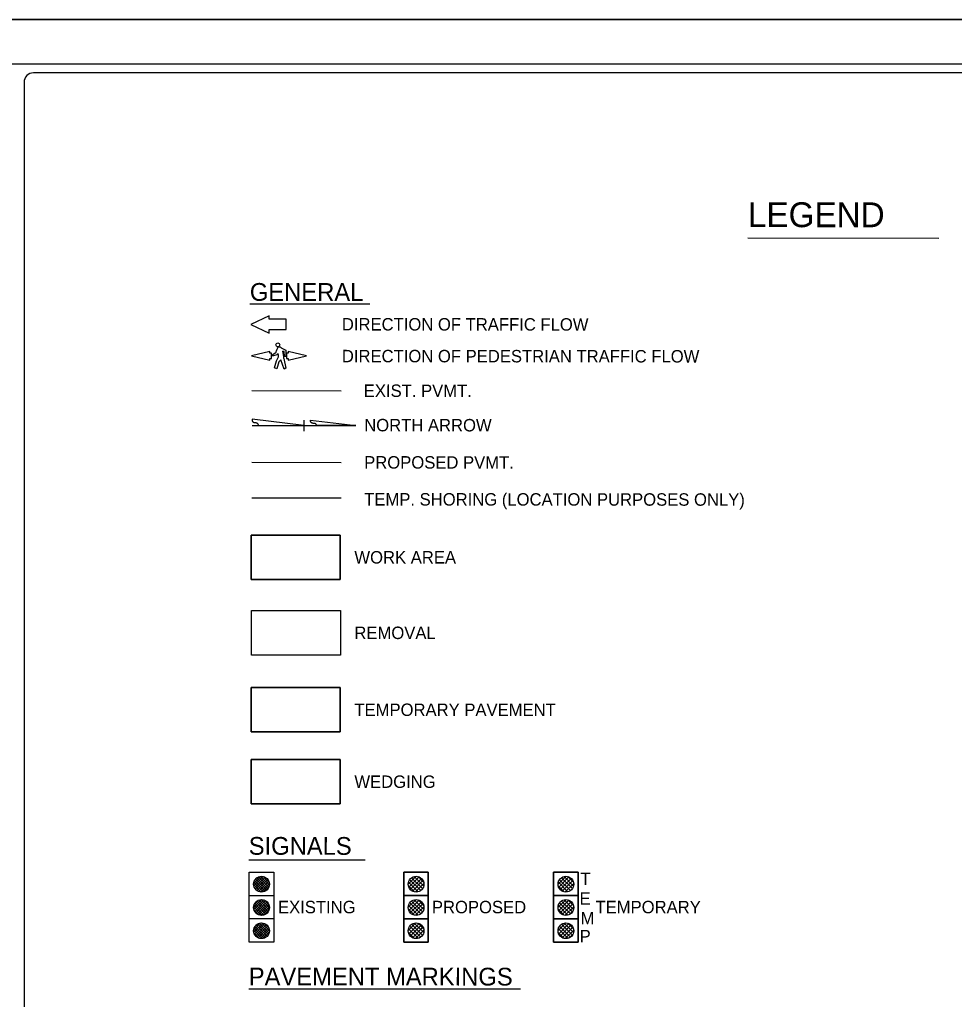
# Model space of a CAD drawing. Extents: x 1403867 to 1405555, y 486423 to 487523.
# Drawn here: x 1404600 to 1405127, y 486971 to 487523 of the extents above; entities that cross this region are included whole.
import ezdxf

# ---------------------------------------------------------------- set-up
doc = ezdxf.new("R2010")
doc.units = 0
for name, color, linetype in [('Black Area Fill Shapes', 7, 'Continuous'), ('DEV BORDER CELL', 7, 'Continuous'), ('DEV SIGNALIZED INTERSECTION CELL', 7, 'Continuous'), ('Gray Area Fill Shapes', 7, 'Continuous'), ('Old_Level_10', 7, 'Continuous'), ('Sheet Plot Border Outside CELL', 7, 'Continuous'), ('Temp Shoring', 7, 'Continuous')]:
    doc.layers.add(name, color=color, linetype=linetype)

msp = doc.modelspace()

# ---------------------------------------------------------------- linework, layer by layer
at = {"layer": 'Black Area Fill Shapes'}
for p, q in [((1404744.88, 487335.56), (1404745.05, 487336.55)), ((1404747.68, 487338.08), (1404750.17, 487336.59)), ((1404750.17, 487336.59), (1404750.2, 487333.12)), ((1404742.39, 487333.93), (1404744.88, 487335.56)), ((1404742.78, 487333.38), (1404742.39, 487333.93)), ((1404745.07, 487334.14), (1404742.78, 487333.38)), ((1404744.95, 487330.73), (1404746.19, 487332.99)), ((1404745.85, 487334.85), (1404745.07, 487334.14)), ((1404747.35, 487331.15), (1404746.38, 487330.17)), ((1404749.33, 487325.96), (1404747.35, 487331.15)), ((1404749.26, 487335.94), (1404748.45, 487336.11)), ((1404749.02, 487332.05), (1404750.3, 487326.64)), ((1404749.49, 487333.12), (1404749.26, 487335.94)), ((1404750.2, 487333.12), (1404749.49, 487333.12)), ((1404743.88, 487326.68), (1404744.95, 487330.73)), ((1404745.21, 487326.25), (1404743.88, 487326.68)), ((1404746.38, 487330.17), (1404745.21, 487326.25)), ((1404750.3, 487326.64), (1404749.33, 487325.96))]:
    msp.add_line(p, q, dxfattribs=at)
for centre, radius, start, end in [((1404748.22, 487336.02), 3.22, 140.1678, 170.5556), ((1404746.39, 487337.54), 0.84, 96.8806, 140.1678), ((1404746.55, 487336.2), 2.19, 59.1458, 96.8806), ((1404740.78, 487332.97), 5.41, 0.2881, 20.3672), ((1404740.78, 487332.97), 8.29, 353.6356, 22.2339)]:
    msp.add_arc(centre, radius, start, end, dxfattribs=at)
at = {"layer": 'DEV BORDER CELL'}
for p, q in [((1405520.08, 487497.72), (1404040.64, 487497.72)), ((1405520.08, 487492.72), (1404608.13, 487492.72)), ((1404602.84, 487487.44), (1404602.84, 486458)), ((1405010.4, 487399.84), (1405117.8, 487399.76)), ((1404729.97, 487362.8), (1404797.57, 487362.76)), ((1404740.89, 487356.07), (1404730.55, 487351.21)), ((1404740.89, 487354.1), (1404740.89, 487356.07)), ((1404750.49, 487354.09), (1404740.89, 487354.1)), ((1404750.48, 487348.3), (1404750.49, 487354.09)), ((1404730.55, 487351.21), (1404740.88, 487346.33)), ((1404740.88, 487346.33), (1404740.88, 487348.31)), ((1404740.88, 487348.31), (1404750.48, 487348.3)), ((1404741.22, 487335.9), (1404730.88, 487333.47)), ((1404730.88, 487333.47), (1404741.21, 487331.03)), ((1404741.21, 487331.03), (1404741.22, 487332.02)), ((1404741.22, 487334.91), (1404741.22, 487335.9)), ((1404742.15, 487334.91), (1404741.22, 487334.91)), ((1404741.22, 487332.02), (1404742.15, 487332.01)), ((1404742.15, 487332.01), (1404742.15, 487334.91)), ((1404751.5, 487334.91), (1404750.57, 487334.91)), ((1404750.57, 487334.91), (1404750.57, 487332.02)), ((1404750.57, 487332.02), (1404751.5, 487332.01)), ((1404751.49, 487331.03), (1404761.84, 487333.46)), ((1404751.5, 487332.01), (1404751.49, 487331.03)), ((1404761.84, 487333.46), (1404751.5, 487335.9)), ((1404751.5, 487335.9), (1404751.5, 487334.91)), ((1404731.17, 487313.91), (1404781.37, 487313.87)), ((1404760.41, 487294.2), (1404731.19, 487297.79)), ((1404731.19, 487294.2), (1404789.63, 487294.2)), ((1404734.64, 487294.21), (1404760.41, 487294.2)), ((1404760.41, 487297.34), (1404760.41, 487291.07)), ((1404764.13, 487297.34), (1404789.63, 487294.2)), ((1404789.63, 487294.2), (1404767.44, 487294.21)), ((1404731.17, 487273.59), (1404781.37, 487273.55)), ((1404729.35, 487049.84), (1404794.93, 487049.79)), ((1404819.15, 487036.23), (1404823.45, 487040.53)), ((1404819.5, 487034.43), (1404825.25, 487040.23)), ((1404826.15, 487032.58), (1404820, 487038.68)), ((1404820.3, 487033.13), (1404826.55, 487039.38)), ((1404827.2, 487033.63), (1404821.05, 487039.78)), ((1404827.85, 487035.08), (1404822.5, 487040.43)), ((1404827.8, 487037.23), (1404824.7, 487040.38)), ((1404903.51, 487036.23), (1404907.81, 487040.53)), ((1404903.86, 487034.43), (1404909.61, 487040.23)), ((1404910.51, 487032.58), (1404904.36, 487038.68)), ((1404904.66, 487033.13), (1404910.91, 487039.38)), ((1404911.56, 487033.63), (1404905.41, 487039.78)), ((1404912.21, 487035.08), (1404906.86, 487040.43)), ((1404912.16, 487037.23), (1404909.06, 487040.38)), ((1404822.65, 487031.78), (1404819.25, 487035.23)), ((1404824.7, 487031.88), (1404819.3, 487037.28)), ((1404821.5, 487032.23), (1404827.45, 487038.13)), ((1404823.15, 487031.78), (1404827.95, 487036.53)), ((1404826.05, 487032.53), (1404827.3, 487033.78)), ((1404907.01, 487031.78), (1404903.61, 487035.23)), ((1404909.06, 487031.88), (1404903.66, 487037.28)), ((1404905.86, 487032.23), (1404911.81, 487038.13)), ((1404907.51, 487031.78), (1404912.31, 487036.53)), ((1404910.41, 487032.53), (1404911.66, 487033.78)), ((1404819.15, 487023.13), (1404823.45, 487027.43)), ((1404822.65, 487018.68), (1404819.25, 487022.13)), ((1404824.7, 487018.78), (1404819.3, 487024.18)), ((1404819.5, 487021.33), (1404825.25, 487027.13)), ((1404826.15, 487019.48), (1404820, 487025.58)), ((1404820.3, 487020.03), (1404826.55, 487026.28)), ((1404827.2, 487020.53), (1404821.05, 487026.68)), ((1404821.5, 487019.13), (1404827.45, 487025.03)), ((1404827.85, 487021.98), (1404822.5, 487027.33)), ((1404823.15, 487018.68), (1404827.95, 487023.43)), ((1404827.8, 487024.13), (1404824.7, 487027.28)), ((1404903.51, 487023.13), (1404907.81, 487027.43)), ((1404907.01, 487018.68), (1404903.61, 487022.13)), ((1404909.06, 487018.78), (1404903.66, 487024.18)), ((1404903.86, 487021.33), (1404909.61, 487027.13)), ((1404910.51, 487019.48), (1404904.36, 487025.58)), ((1404904.66, 487020.03), (1404910.91, 487026.28)), ((1404911.56, 487020.53), (1404905.41, 487026.68)), ((1404905.86, 487019.13), (1404911.81, 487025.03)), ((1404912.21, 487021.98), (1404906.86, 487027.33)), ((1404907.51, 487018.68), (1404912.31, 487023.43)), ((1404912.16, 487024.13), (1404909.06, 487027.28)), ((1404826.05, 487019.43), (1404827.3, 487020.68)), ((1404910.41, 487019.43), (1404911.66, 487020.68)), ((1404819.15, 487010.03), (1404823.45, 487014.33)), ((1404824.7, 487005.68), (1404819.3, 487011.08)), ((1404819.5, 487008.23), (1404825.25, 487014.03)), ((1404826.15, 487006.38), (1404820, 487012.48)), ((1404820.3, 487006.93), (1404826.55, 487013.18)), ((1404827.2, 487007.43), (1404821.05, 487013.58)), ((1404821.5, 487006.03), (1404827.45, 487011.93)), ((1404827.85, 487008.88), (1404822.5, 487014.23)), ((1404827.8, 487011.03), (1404824.7, 487014.18)), ((1404903.51, 487010.03), (1404907.81, 487014.33)), ((1404909.06, 487005.68), (1404903.66, 487011.08)), ((1404903.86, 487008.23), (1404909.61, 487014.03)), ((1404910.51, 487006.38), (1404904.36, 487012.48)), ((1404904.66, 487006.93), (1404910.91, 487013.18)), ((1404911.56, 487007.43), (1404905.41, 487013.58)), ((1404905.86, 487006.03), (1404911.81, 487011.93)), ((1404912.21, 487008.88), (1404906.86, 487014.23)), ((1404912.16, 487011.03), (1404909.06, 487014.18)), ((1404822.65, 487005.58), (1404819.25, 487009.03)), ((1404823.15, 487005.58), (1404827.95, 487010.33)), ((1404826.05, 487006.33), (1404827.3, 487007.58)), ((1404907.01, 487005.58), (1404903.61, 487009.03)), ((1404907.51, 487005.58), (1404912.31, 487010.33)), ((1404910.41, 487006.33), (1404911.66, 487007.58)), ((1404729.35, 486977.29), (1404882.4, 486977.18))]:
    msp.add_line(p, q, dxfattribs=at)
for points in [[(1404780.76, 487232.61), (1404730.76, 487232.61), (1404730.76, 487207.61), (1404780.76, 487207.61)], [(1404730.76, 487232.61), (1404780.76, 487232.61), (1404780.76, 487207.61), (1404730.76, 487207.61)], [(1404730.98, 487190.1), (1404780.98, 487190.1), (1404780.98, 487165.1), (1404730.98, 487165.1)], [(1404730.98, 487190.1), (1404780.98, 487190.1), (1404780.98, 487165.1), (1404730.98, 487165.1)], [(1404730.98, 487190.1), (1404780.98, 487190.1), (1404780.98, 487165.1), (1404730.98, 487165.1)], [(1404730.76, 487146.81), (1404780.76, 487146.81), (1404780.76, 487121.81), (1404730.76, 487121.81)], [(1404730.76, 487106.33), (1404780.76, 487106.33), (1404780.76, 487081.33), (1404730.76, 487081.33)], [(1404816.65, 487029.73), (1404830.45, 487029.73), (1404830.45, 487042.83), (1404816.65, 487042.83)], [(1404901.01, 487029.73), (1404914.81, 487029.73), (1404914.81, 487042.83), (1404901.01, 487042.83)], [(1404816.65, 487016.63), (1404830.45, 487016.63), (1404830.45, 487029.73), (1404816.65, 487029.73)], [(1404901.01, 487016.63), (1404914.81, 487016.63), (1404914.81, 487029.73), (1404901.01, 487029.73)], [(1404816.65, 487003.53), (1404830.45, 487003.53), (1404830.45, 487016.63), (1404816.65, 487016.63)], [(1404901.01, 487003.53), (1404914.81, 487003.53), (1404914.81, 487016.63), (1404901.01, 487016.63)]]:
    msp.add_lwpolyline(points, close=True, dxfattribs=at)
for centre, radius in [((1404745.73, 487339.67), 1.11), ((1404823.55, 487036.13), 4.44), ((1404907.91, 487036.13), 4.44), ((1404823.55, 487023.03), 4.44), ((1404907.91, 487023.03), 4.44), ((1404823.55, 487009.93), 4.44), ((1404907.91, 487009.93), 4.44)]:
    msp.add_circle(centre, radius, dxfattribs=at)
msp.add_arc((1404608.12, 487487.44), 5.29, 89.9972, 180, dxfattribs=at)
for points in [[(1404731.19, 487297.79), (1404731.09, 487295.98), (1404734.67, 487295.92), (1404734.64, 487294.21)], [(1404767.44, 487294.2), (1404767.61, 487295.46), (1404764.03, 487295.52), (1404764.13, 487297.34)]]:
    msp.add_open_spline(points, degree=2, dxfattribs=at)
at = {"layer": 'DEV SIGNALIZED INTERSECTION CELL'}
for p, q in [((1404729.66, 487042.83), (1404743.46, 487042.83)), ((1404729.66, 487029.73), (1404729.66, 487042.83)), ((1404732.14, 487036.45), (1404736.24, 487040.56)), ((1404732.24, 487035.14), (1404737.56, 487040.46)), ((1404732.62, 487034.1), (1404738.59, 487040.08)), ((1404732.88, 487038.6), (1404734.09, 487039.82)), ((1404733.18, 487033.25), (1404739.44, 487039.51)), ((1404733.24, 487039.08), (1404739.51, 487032.81)), ((1404733.91, 487032.57), (1404740.12, 487038.78)), ((1404733.99, 487039.75), (1404740.18, 487033.56)), ((1404734.9, 487040.25), (1404740.68, 487034.47)), ((1404736.02, 487040.54), (1404740.97, 487035.59)), ((1404737.51, 487040.47), (1404740.9, 487037.08)), ((1404743.46, 487042.83), (1404743.46, 487029.73)), ((1404732.13, 487035.95), (1404736.38, 487031.7)), ((1404732.26, 487037.23), (1404737.66, 487031.83)), ((1404732.66, 487038.24), (1404738.67, 487032.23)), ((1404732.68, 487033.98), (1404734.41, 487032.25)), ((1404734.81, 487032.05), (1404740.64, 487037.88)), ((1404735.91, 487031.74), (1404740.95, 487036.78)), ((1404737.35, 487031.76), (1404740.93, 487035.34)), ((1404729.66, 487029.73), (1404743.46, 487029.73)), ((1404729.66, 487016.63), (1404729.66, 487029.73)), ((1404743.46, 487029.73), (1404743.46, 487016.63)), ((1404732.12, 487023.07), (1404736.52, 487027.47)), ((1404732.13, 487023.17), (1404736.7, 487018.6)), ((1404732.29, 487021.83), (1404737.77, 487027.3)), ((1404732.33, 487024.38), (1404737.91, 487018.8)), ((1404732.54, 487024.9), (1404734.69, 487027.06)), ((1404732.71, 487020.83), (1404738.76, 487026.88)), ((1404732.78, 487025.35), (1404738.88, 487019.25)), ((1404733.31, 487020.01), (1404739.58, 487026.28)), ((1404733.4, 487026.14), (1404739.67, 487019.87)), ((1404734.07, 487019.36), (1404740.23, 487025.52)), ((1404734.18, 487026.77), (1404740.31, 487020.65)), ((1404735, 487018.88), (1404740.72, 487024.59)), ((1404735.13, 487027.23), (1404740.76, 487021.6)), ((1404736.15, 487018.61), (1404740.98, 487023.44)), ((1404736.32, 487027.46), (1404740.99, 487022.79)), ((1404737.95, 487027.25), (1404740.78, 487024.42)), ((1404743.46, 487016.63), (1404729.66, 487016.63)), ((1404729.66, 487003.53), (1404729.66, 487016.63)), ((1404732.41, 487021.48), (1404735.01, 487018.87)), ((1404737.69, 487018.74), (1404740.85, 487021.9)), ((1404743.46, 487016.63), (1404743.46, 487003.53)), ((1404732.15, 487010.43), (1404736.06, 487014.34)), ((1404732.21, 487009.07), (1404737.42, 487014.29)), ((1404732.39, 487011.43), (1404738.07, 487005.76)), ((1404732.56, 487008.01), (1404738.48, 487013.93)), ((1404732.86, 487012.38), (1404739.01, 487006.23)), ((1404733.11, 487007.15), (1404739.35, 487013.39)), ((1404733.5, 487013.15), (1404739.78, 487006.87)), ((1404733.82, 487006.44), (1404740.05, 487012.67)), ((1404734.31, 487013.75), (1404740.39, 487007.68)), ((1404734.7, 487005.91), (1404740.59, 487011.8)), ((1404735.29, 487014.18), (1404740.81, 487008.66)), ((1404736.52, 487014.37), (1404741, 487009.89)), ((1404738.29, 487014.02), (1404740.65, 487011.66)), ((1404732.14, 487010.27), (1404736.9, 487005.51)), ((1404732.3, 487008.69), (1404735.32, 487005.67)), ((1404735.77, 487005.56), (1404740.93, 487010.72)), ((1404737.15, 487005.53), (1404740.96, 487009.34)), ((1404743.46, 487003.53), (1404729.66, 487003.53))]:
    msp.add_line(p, q, dxfattribs=at)
for centre in [(1404736.56, 487036.13), (1404736.56, 487023.03), (1404736.56, 487009.93)]:
    msp.add_circle(centre, 4.44, dxfattribs=at)
at = {"layer": 'Gray Area Fill Shapes'}
for points in [[(1404730.76, 487207.61), (1404780.76, 487207.61), (1404780.76, 487232.61), (1404730.76, 487232.61)], [(1404816.65, 487042.83), (1404830.45, 487042.83), (1404830.45, 487003.53), (1404816.65, 487003.53)], [(1404901.01, 487042.83), (1404914.81, 487042.83), (1404914.81, 487003.53), (1404901.01, 487003.53)]]:
    msp.add_lwpolyline(points, close=True, dxfattribs=at)
at = {"layer": 'Old_Level_10'}
for points in [[(1404730.76, 487121.81), (1404780.76, 487121.81), (1404780.76, 487146.81), (1404730.76, 487146.81), (1404730.76, 487121.81)], [(1404730.76, 487081.33), (1404780.76, 487081.33), (1404780.76, 487106.33), (1404730.76, 487106.33), (1404730.76, 487081.33)]]:
    msp.add_lwpolyline(points, dxfattribs=at)
at = {"layer": 'Sheet Plot Border Outside CELL'}
for points in [[(1403867.36, 486422.72), (1403867.36, 487522.72), (1405555.36, 487522.72), (1405555.36, 486422.72)], [(1403867.36, 487522.72), (1405555.36, 487522.72), (1405555.36, 486422.72), (1403867.36, 486422.72)], [(1403867.36, 486422.72), (1405555.36, 486422.72), (1405555.36, 487522.72), (1403867.36, 487522.72)]]:
    msp.add_lwpolyline(points, close=True, dxfattribs=at)
at = {"layer": 'Temp Shoring'}
msp.add_line((1404731.17, 487253.56), (1404781.37, 487253.56), dxfattribs=at)

# ---------------------------------------------------------------- texts
at = {"layer": 'DEV BORDER CELL'}
for s, height, rotation, p in [('LEGEND', 13.999, 359.9598, (1405010.37, 487405.92)), ('GENERAL', 10, 359.9598, (1404729.97, 487364.45)), ('DIRECTION OF TRAFFIC FLOW', 7, 359.9598, (1404781.77, 487347.76)), ('DIRECTION OF PEDESTRIAN TRAFFIC FLOW', 7, 359.9598, (1404781.77, 487329.87)), ('EXIST. PVMT.', 7, 359.9598, (1404794.11, 487310.37)), ('NORTH ARROW', 7, 359.9598, (1404794.35, 487291)), ('PROPOSED PVMT.', 7, 359.9598, (1404794.34, 487270.05)), ('TEMP. SHORING (LOCATION PURPOSES ONLY)', 7, 359.9598, (1404794.34, 487249.26)), ('WORK AREA', 7, 360, (1404788.83, 487216.61)), ('REMOVAL', 7, 360, (1404788.83, 487174.1)), ('TEMPORARY PAVEMENT', 7, 360, (1404788.83, 487130.81)), ('WEDGING', 7, 360, (1404788.83, 487090.33)), ('SIGNALS', 10, 359.9598, (1404729.35, 487052.7)), ('EXISTING', 7, 359.9598, (1404745.82, 487019.79)), ('PROPOSED', 7, 359.9598, (1404832.47, 487019.79)), ('TEMPORARY ', 7, 359.9598, (1404924.55, 487019.79)), ('PAVEMENT MARKINGS', 10, 359.9598, (1404729.35, 486979.21))]:
    msp.add_text(s, height=height, rotation=rotation, dxfattribs=at).set_placement(p)
for s, p in [('T', (1404916.06, 487035.67)), ('T', (1404916.06, 487035.67)), ('E', (1404915.57, 487024.61)), ('E', (1404915.57, 487024.61)), ('M', (1404916.13, 487013.57)), ('M', (1404916.13, 487013.57)), ('P', (1404915.64, 487003.39)), ('P', (1404915.64, 487003.39))]:
    msp.add_text(s, height=7, dxfattribs=at).set_placement(p)

doc.saveas('drawing.dxf')
